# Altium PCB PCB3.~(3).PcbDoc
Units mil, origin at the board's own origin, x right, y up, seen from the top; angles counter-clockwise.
Board outline 2315 x 1830 mil, 2 copper layers (Top Layer, Bottom Layer); 11 components, 12 nets, 36 pads, 0 vias.
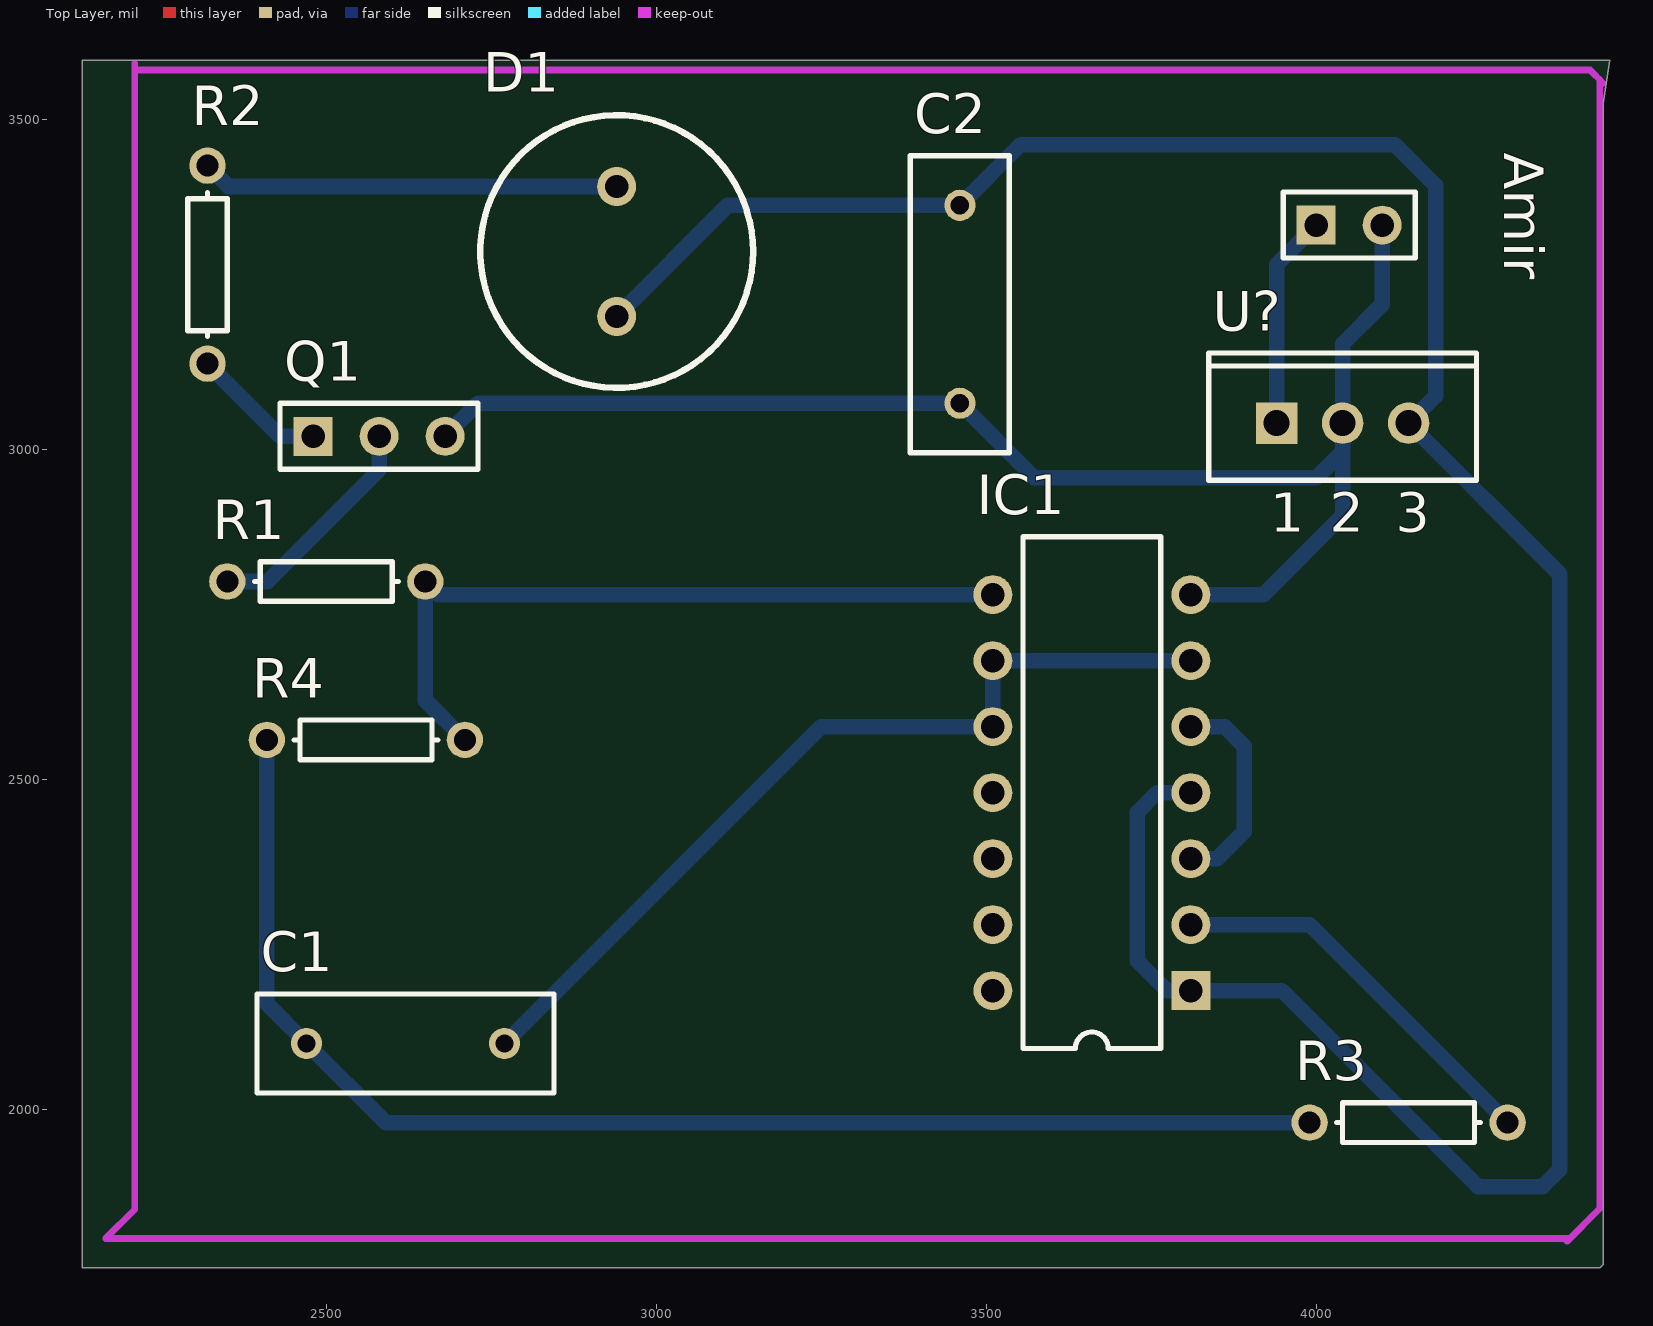
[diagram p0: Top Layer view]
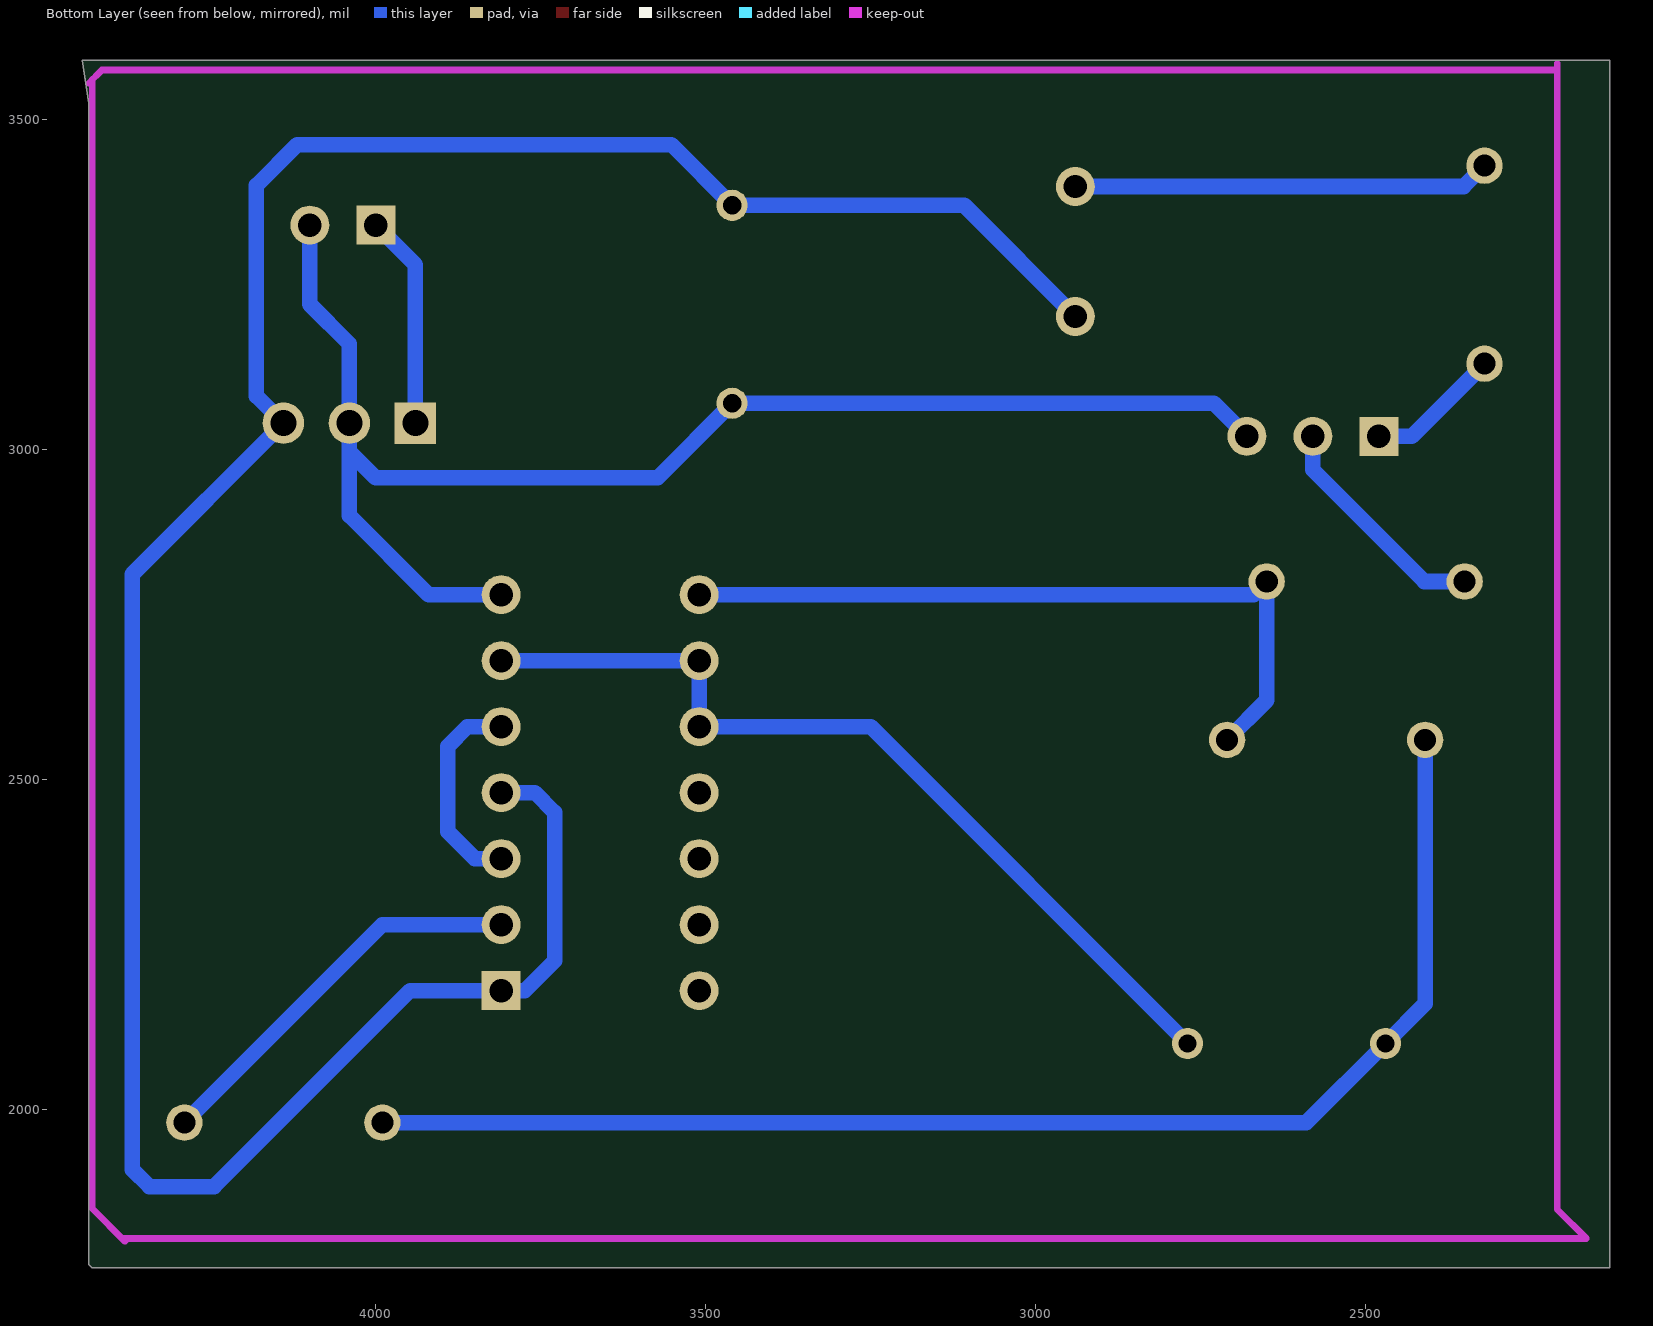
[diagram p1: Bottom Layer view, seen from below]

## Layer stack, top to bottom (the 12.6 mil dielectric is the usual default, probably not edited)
Top Layer: signal copper 1.4
Dielectric: dielectric 12.6, FR-4, Dk 4.8
Bottom Layer: signal copper 1.4

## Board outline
4435,3525 4435,1765 4430,1760 2130,1760 2130,3590 4445,3590

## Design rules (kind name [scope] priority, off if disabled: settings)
Clearance [All] p1: gap=39.37
PolygonConnect [All] p1: connectstyle=Relief reliefconductorwidth=10 reliefentries=4 polygonreliefangle="90 Angle"
RoutingLayers [All] p1: top layer_v5=FALSE bottom layer_v5=TRUE
RoutingVias [All] p1: holewidth=28 width=50 viastyle="Through Hole" minholewidth=28 minwidth=50 maxholewidth=28 maxwidth=50
SilkscreenOverComponentPads [All] p1: minsilkscreentomaskgap=10
SolderMaskExpansion [All] p1: expansion=4
Width [All] p1: maxlimit=23.62 minlimit=23.62 preferedwidth=23.62 minimp=50.000000 maximp=50.000000 favimp=50.000000
26 further rules are at their usual default settings.

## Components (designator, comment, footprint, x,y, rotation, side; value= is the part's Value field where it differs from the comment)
Amir "Header 2" HDR1X2 4000,3340 r0 top
C1 "Cap" RAD-0.3 2620,2100 r0 top
C2 "Cap" RAD-0.3 3460,3220 r90 top
D1 "LED0" RB5-10.5 2940,3300 r90 top
IC1 "MC74HC00AN" 646-06 3660,2480 r90 top
Q1 "NPN" HDR1X3 2480,3020 r0 top
R1 "Res1" AXIAL-0.3 2500,2800 r180 top
R2 "Res1" AXIAL-0.3 2320,3280 r90 top
R3 "Res1" AXIAL-0.3 4140,1980 r0 top
R4 "Res1" AXIAL-0.3 2560,2560 r0 top
U? "MC7805ACT" 221A-04 4040,3040 r0 top

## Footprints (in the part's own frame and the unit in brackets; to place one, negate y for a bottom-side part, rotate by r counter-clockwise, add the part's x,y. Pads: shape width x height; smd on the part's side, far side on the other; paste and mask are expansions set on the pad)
221A-04 [mm] "TO, Thru-Hole, Vertical, Heatsink Mounted; 3 In-Line Leads; Pitch 2.54 mm"
  rect 1.6x1.6 hole 1: 1(-2.54,0)
  round 1.6 hole 1: 2(0,0) 3(2.54,0)
  silkscreen extent -5.15,-2.2 5.15,2.7
646-06 [mm] "DIP; 14 Leads; Row Spacing 7.62 mm; Pitch 2.54 mm"
  rect 1.5x1.5 hole 0.9: 1(-7.62,-3.81)
  round 1.5 hole 0.9: 2(-5.08,-3.81) 3(-2.54,-3.81) 4(0,-3.81) 5(2.54,-3.81) 6(5.08,-3.81) 7(7.62,-3.81) 8(7.62,3.81) 9(5.08,3.81) 10(2.54,3.81) 11(0,3.81) 12(-2.54,3.81) 13(-5.08,3.81) 14(-7.62,3.81)
  silkscreen extent -9.85,-2.65 9.85,2.65
AXIAL-0.3 [mm] "Axial Device, Thru-Hole; 2 Leads; 0.3 in Pin Spacing"
  round 1.4 hole 0.85: 1(-3.81,0) 2(3.81,0)
  silkscreen extent -2.77,-0.76 2.77,0.76
HDR1X2 [mm] "Connector; Header; 2 Position"
  rect 1.5x1.5 hole 0.9: 1(0,0)
  round 1.5 hole 0.9: 2(2.54,0)
  silkscreen extent -1.27,-1.27 3.81,1.27
HDR1X3 [mm] "Connector; Header; 3 Position"
  rect 1.5x1.5 hole 0.9: 1(0,0)
  round 1.5 hole 0.9: 2(2.54,0) 3(5.08,0)
  silkscreen extent -1.27,-1.27 6.35,1.27
RAD-0.3 [mm] "Radial Cap, Thru-Hole; 2 Leads; 0.3 in Pin Spacing"
  round 1.2 hole 0.7: 1(-3.81,0) 2(3.81,0)
  silkscreen extent -5.71,-1.91 5.71,1.91
RB5-10.5 [mm] "Motor, General Kind; 2 Leads"
  round 1.5 hole 0.9: 1(-2.5,0) 2(2.5,0)
  silkscreen extent -5.25,-5.25 5.25,5.25

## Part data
Amir: "Header, 2-Pin"
C1 C2: "Capacitor"
D1: "Typical INFRARED GaAs LED"
IC1: "Quad 2-Input NAND Gate"
Q1: "NPN Bipolar Transistor"
R1 R2 R3 R4: "Resistor"
U?: "3-Terminal Positive Fixed Voltage Regulator"

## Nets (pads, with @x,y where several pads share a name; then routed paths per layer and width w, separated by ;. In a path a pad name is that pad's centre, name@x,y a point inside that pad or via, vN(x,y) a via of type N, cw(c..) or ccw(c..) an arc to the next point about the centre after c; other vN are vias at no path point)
GND: Amir.2 C2.1 IC1.7 Q1.3 U?.2 | length 2231.6
  Bottom Layer w23.62: Q1.3 2730,3070 C2.1 3573,2957 4000,2957 4040,2997 ; IC1.7 3920,2780 4040,2900 4040,2997 ; Amir.2 4100,3220 4040,3160 U?.2 ; 4040,2997 U?.2 ; 4040,2997 U?.2
NET1: IC1.8 R1.1 R4.2 | length 1133.1
  Bottom Layer w23.62: R4.2 2650,2620 R1.1 2670,2780 IC1.8
NetAmir_1: Amir.1 U?.1 | length 324.9
  Bottom Layer w23.62: U?.1 3940,3280 Amir.1
NetC1_1: C1.1 R3.1 R4.1 | length 2054.6
  Bottom Layer w23.62: R4.1 2410,2160 C1.1 2590,1980 R3.1
NetC1_2: C1.2 IC1.6 IC1.9 IC1.10 | length 1338.8
  Bottom Layer w23.62: C1.2 3250,2580 IC1.10 IC1.9 IC1.6
NetD1_2: D1.2 R2.2 | length 633.1
  Bottom Layer w23.62: R2.2 2351.57,3398.43 D1.2
NetIC1_2: IC1.2 R3.2 | length 604.3
  Bottom Layer w23.62: IC1.2 3990,2280 R3.2
NetIC1_3: IC1.3 IC1.5 | length 320.4
  Bottom Layer w23.62: IC1.3 3850,2380 3891,2421 3891,2550 3861,2580 IC1.5
NetQ1_1: Q1.1 R2.1 | length 205.6
  Bottom Layer w23.62: R2.1 2430,3020 Q1.1
NetQ1_2: Q1.2 R1.2 | length 351
  Bottom Layer w23.62: R1.2 2411,2800 2580,2969 Q1.2
PHL: C2.2 D1.1 IC1.1 IC1.4 U?.3 | length 4088.2
  Bottom Layer w23.62: D1.1 3108.43,3370 C2.2 3552,3462 4119,3462 4181,3400 4181,3081 U?.3 4369,2811 4369,1909 4343,1883 4245,1883 3948,2180 IC1.1 3774,2180 3729,2225 3729,2450 3759,2480 IC1.4
VDD: IC1.14
pads on no net: IC1.11 IC1.12 IC1.13

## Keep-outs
Keep-Out Layer:
  lines w10: 2210,3575 4415,3575 4435,3555 ; 2210,3585 2210,1848.77 2165.61,1804.39 4384.39,1804.39 ; 4380,1800 4429.39,1849.39 4429.39,3560.61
